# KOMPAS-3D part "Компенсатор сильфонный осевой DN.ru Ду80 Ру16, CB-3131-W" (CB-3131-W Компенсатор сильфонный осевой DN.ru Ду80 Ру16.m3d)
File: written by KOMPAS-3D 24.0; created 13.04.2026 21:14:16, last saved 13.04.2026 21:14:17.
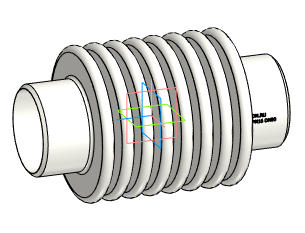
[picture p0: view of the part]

Document properties: Автор: DN.RU; Полное имя файла: D:\PROJECT CAD\DN.RU\...197(ACTUALE). CB-3131-W Компенсатор сильфонный осевой DN.ru\Исходники\DN80\CB-3131-W Компенсатор сильфонный осевой DN.ru Ду80 Ру16_1.m3d

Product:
- Body: Твердое тело1  | qty 1
    Масса: 2.588149
- Part/product: Компенсатор сильфонный осевой DN.ru Ду80 Ру16  | designation CB-3131-W
    Масса: 2.1
    Раздел спецификации: Прочие изделия
    Комментарий: D140-02123
    Примечание: D140-02123
    additional columns: Типовые

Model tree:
1. Твердое тело1  (labels: Твердое тело1)

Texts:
  CB-3131-W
